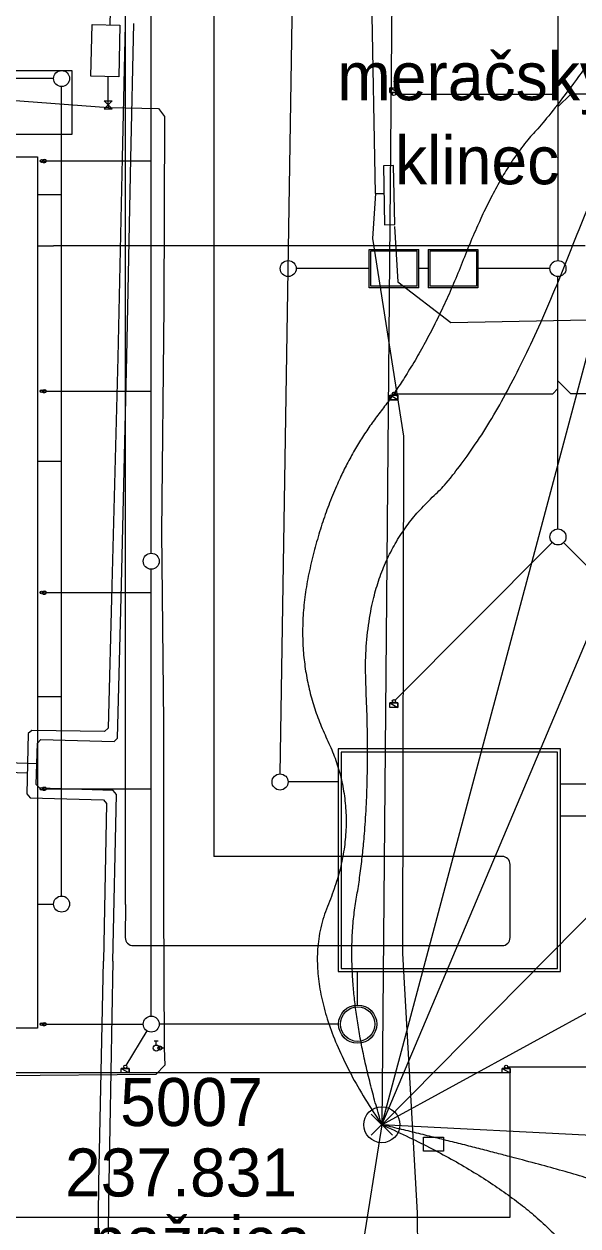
# Model space of a CAD drawing. Extents: x -264090 to -263500, y -1242327 to -1242030.
# Drawn here: x -263959.9 to -263925.3, y -1242264.5 to -1242189.5 of the extents above; entities that cross this region are included whole.
import ezdxf

# ---------------------------------------------------------------- set-up
doc = ezdxf.new("R2010")
doc.units = 0
for name, color, linetype in [('KFA_KOORD_SIT_a_IS_SEDA', 7, 'Continuous'), ('KFA_ZVS_BOD_CISLO', 7, 'Continuous'), ('KFA_ZVS_BOD_SYMBOL', 7, 'Continuous'), ('KFA_ZVS_BOD_VYSKA', 7, 'Continuous'), ('KFA_ZVS_NIVELACIA', 7, 'Continuous'), ('KFA_ZVS_POPIS', 7, 'Continuous'), ('KFA_ZVS_SMERY_A_DLZKY', 7, 'Continuous')]:
    doc.layers.add(name, color=color, linetype=linetype)

msp = doc.modelspace()

# ---------------------------------------------------------------- linework, layer by layer
at = {"layer": 'KFA_KOORD_SIT_a_IS_SEDA'}
for p, q in [((-263948.093, -1242087.901), (-263948.093, -1242241.458)), ((-263953.617, -1242244.458), (-263953.617, -1242093.307)), ((-263937.993, -1242200.068), (-263938.95, -1242148.666)), ((-263926.593, -1242155.252), (-263926.593, -1242204.252)), ((-263952, -1242222.527), (-263952, -1242182)), ((-263953.528, -1242183.799), (-263953.63, -1242189.514)), ((-263943.946, -1242236.311), (-263943.136, -1242185.245)), ((-263954.57, -1242189.535), (-263954.509, -1242186.913)), ((-263955.775, -1242192.739), (-263955.679, -1242189.503)), ((-263955.679, -1242189.503), (-263953.955, -1242189.552)), ((-263953.955, -1242189.552), (-263954.033, -1242192.766)), ((-263953.63, -1242189.514), (-263953.822, -1242197.849)), ((-263953.266, -1242197.902), (-263953.083, -1242189.456)), ((-263958.097, -1242192.883), (-263969.542, -1242192.883)), ((-263954.033, -1242192.766), (-263955.775, -1242192.739)), ((-263954.693, -1242194.518), (-263954.696, -1242192.756)), ((-263957.597, -1242243.932), (-263957.597, -1242193.383)), ((-263937.093, -1242193.752), (-263937.093, -1242193.462)), ((-263937.093, -1242193.462), (-263936.593, -1242193.462)), ((-263936.593, -1242193.752), (-263937.093, -1242193.462)), ((-263936.593, -1242193.752), (-263937.093, -1242193.462)), ((-263937.093, -1242193.462), (-263937.093, -1242193.752)), ((-263936.593, -1242193.752), (-263937.093, -1242193.752)), ((-263937.093, -1242193.752), (-263936.593, -1242193.752)), ((-263936.743, -1242193.852), (-263926.953, -1242193.852)), ((-263936.593, -1242193.462), (-263936.593, -1242193.752)), ((-263926.953, -1242193.852), (-263926.593, -1242194.178)), ((-263925.798, -1242193.852), (-263926.593, -1242194.648)), ((-263920.944, -1242193.852), (-263925.798, -1242193.852)), ((-263961.65, -1242194.164), (-263954.663, -1242194.7)), ((-263954.943, -1242194.268), (-263954.443, -1242194.268)), ((-263954.443, -1242194.268), (-263954.943, -1242194.768)), ((-263954.443, -1242194.768), (-263954.943, -1242194.268)), ((-263954.943, -1242194.768), (-263954.443, -1242194.768)), ((-263954.663, -1242194.7), (-263954.693, -1242194.518)), ((-263954.663, -1242194.7), (-263951.539, -1242194.754)), ((-263951.539, -1242194.754), (-263951.176, -1242195.243)), ((-263951.176, -1242195.243), (-263951.207, -1242207.105)), ((-263967.593, -1242197.782), (-263959.093, -1242197.782)), ((-263967.593, -1242197.782), (-263959.097, -1242197.782)), ((-263959.097, -1242197.782), (-263959.093, -1242252.182)), ((-263959.093, -1242197.782), (-263959.093, -1242252.182)), ((-263958.799, -1242197.962), (-263958.762, -1242197.962)), ((-263958.799, -1242198.102), (-263958.762, -1242198.102)), ((-263958.762, -1242197.962), (-263958.742, -1242197.942)), ((-263958.762, -1242198.102), (-263958.742, -1242198.122)), ((-263958.742, -1242197.942), (-263958.637, -1242197.942)), ((-263958.742, -1242198.122), (-263958.637, -1242198.122)), ((-263958.575, -1242198.032), (-263952, -1242198.032)), ((-263953.822, -1242197.849), (-263954.091, -1242210.31)), ((-263953.525, -1242210.24), (-263953.266, -1242197.902)), ((-263936.861, -1242198.305), (-263937.501, -1242198.334)), ((-263937.501, -1242198.334), (-263937.428, -1242202.028)), ((-263937.501, -1242198.334), (-263937.501, -1242198.334)), ((-263936.776, -1242202.003), (-263936.861, -1242198.305)), ((-263937.993, -1242200.068), (-263938.174, -1242202.878)), ((-263937.993, -1242200.068), (-263937.467, -1242200.068)), ((-263959.097, -1242200.132), (-263957.597, -1242200.132)), ((-263937.428, -1242202.028), (-263936.776, -1242202.003)), ((-263936.81, -1242202.117), (-263936.602, -1242205.569)), ((-263938.174, -1242202.878), (-263936.242, -1242215.207)), ((-263959.097, -1242203.332), (-263958.097, -1242203.332)), ((-263924.893, -1242203.332), (-263958.097, -1242203.332)), ((-263938.393, -1242203.552), (-263935.293, -1242203.552)), ((-263938.393, -1242205.952), (-263938.393, -1242203.552)), ((-263938.293, -1242205.852), (-263938.293, -1242203.652)), ((-263938.293, -1242203.652), (-263935.393, -1242203.652)), ((-263935.393, -1242205.852), (-263935.393, -1242203.652)), ((-263935.293, -1242205.952), (-263935.293, -1242203.552)), ((-263934.693, -1242203.552), (-263931.593, -1242203.552)), ((-263934.693, -1242203.552), (-263934.693, -1242205.952)), ((-263934.593, -1242203.652), (-263934.593, -1242205.852)), ((-263934.593, -1242203.652), (-263931.693, -1242203.652)), ((-263931.693, -1242203.652), (-263931.693, -1242205.852)), ((-263931.593, -1242203.552), (-263931.593, -1242205.952)), ((-263938.393, -1242204.752), (-263942.945, -1242204.752)), ((-263934.693, -1242204.752), (-263935.293, -1242204.752)), ((-263927.093, -1242204.752), (-263931.593, -1242204.752)), ((-263926.593, -1242221.011), (-263926.593, -1242205.252)), ((-263935.293, -1242205.952), (-263938.393, -1242205.952)), ((-263935.393, -1242205.852), (-263938.293, -1242205.852)), ((-263936.602, -1242205.569), (-263933.291, -1242208.127)), ((-263931.593, -1242205.952), (-263934.693, -1242205.952)), ((-263931.693, -1242205.852), (-263934.593, -1242205.852)), ((-263951.207, -1242207.105), (-263951.356, -1242221.201)), ((-263933.291, -1242208.127), (-263902.954, -1242207.498)), ((-263954.091, -1242210.31), (-263954.451, -1242224.536)), ((-263953.851, -1242224.476), (-263953.525, -1242210.24)), ((-263925.798, -1242212.562), (-263926.593, -1242211.767)), ((-263958.799, -1242212.337), (-263958.762, -1242212.337)), ((-263958.799, -1242212.477), (-263958.762, -1242212.477)), ((-263958.762, -1242212.337), (-263958.742, -1242212.317)), ((-263958.762, -1242212.477), (-263958.742, -1242212.497)), ((-263958.742, -1242212.317), (-263958.637, -1242212.317)), ((-263958.742, -1242212.497), (-263958.637, -1242212.497)), ((-263958.575, -1242212.407), (-263952, -1242212.407)), ((-263937.093, -1242212.952), (-263937.093, -1242212.662)), ((-263937.093, -1242212.662), (-263936.593, -1242212.662)), ((-263936.593, -1242212.952), (-263937.093, -1242212.662)), ((-263936.593, -1242212.952), (-263937.093, -1242212.662)), ((-263937.093, -1242212.662), (-263937.093, -1242212.952)), ((-263936.743, -1242212.562), (-263926.919, -1242212.562)), ((-263936.593, -1242212.662), (-263936.593, -1242212.952)), ((-263926.919, -1242212.562), (-263926.593, -1242212.237)), ((-263916.443, -1242212.562), (-263925.798, -1242212.562)), ((-263936.593, -1242212.952), (-263937.093, -1242212.952)), ((-263937.093, -1242212.952), (-263936.593, -1242212.952)), ((-263936.242, -1242215.207), (-263936.305, -1242247.518)), ((-263959.097, -1242216.782), (-263957.597, -1242216.782)), ((-263951.356, -1242221.201), (-263951.228, -1242233.09)), ((-263936.772, -1242231.691), (-263926.947, -1242221.865)), ((-263916.414, -1242231.691), (-263926.24, -1242221.865)), ((-263952, -1242251.432), (-263952, -1242223.527)), ((-263954.451, -1242224.536), (-263954.692, -1242233.447)), ((-263954.106, -1242234.073), (-263953.851, -1242224.476)), ((-263958.799, -1242224.912), (-263958.762, -1242224.912)), ((-263958.799, -1242225.052), (-263958.762, -1242225.052)), ((-263958.762, -1242224.912), (-263958.742, -1242224.892)), ((-263958.762, -1242225.052), (-263958.742, -1242225.072)), ((-263958.742, -1242224.892), (-263958.637, -1242224.892)), ((-263958.742, -1242225.072), (-263958.637, -1242225.072)), ((-263958.575, -1242224.982), (-263952, -1242224.982)), ((-263959.097, -1242231.482), (-263957.597, -1242231.482)), ((-263937.093, -1242231.862), (-263936.593, -1242231.862)), ((-263937.093, -1242232.152), (-263937.093, -1242231.862)), ((-263937.093, -1242231.862), (-263936.593, -1242232.152)), ((-263937.093, -1242231.862), (-263936.593, -1242232.152)), ((-263936.593, -1242231.862), (-263937.093, -1242231.862)), ((-263936.593, -1242232.152), (-263937.093, -1242232.152)), ((-263936.593, -1242231.862), (-263936.593, -1242232.152)), ((-263936.593, -1242232.152), (-263936.593, -1242231.862)), ((-263951.228, -1242233.09), (-263951.241, -1242244.319)), ((-263959.696, -1242233.784), (-263959.771, -1242237.559)), ((-263959.451, -1242233.59), (-263959.696, -1242233.784)), ((-263954.912, -1242233.658), (-263959.451, -1242233.59)), ((-263954.692, -1242233.447), (-263954.912, -1242233.658)), ((-263959.189, -1242236.963), (-263959.11, -1242234.394)), ((-263959.11, -1242234.394), (-263958.895, -1242234.164)), ((-263958.895, -1242234.164), (-263954.308, -1242234.275)), ((-263954.308, -1242234.275), (-263954.106, -1242234.073)), ((-263926.43, -1242234.749), (-263940.33, -1242234.749)), ((-263940.33, -1242234.749), (-263940.33, -1242248.649)), ((-263926.63, -1242234.949), (-263940.13, -1242234.949)), ((-263940.13, -1242234.949), (-263940.13, -1242248.449)), ((-263926.63, -1242248.449), (-263926.63, -1242234.949)), ((-263926.43, -1242248.649), (-263926.43, -1242234.749)), ((-263959.149, -1242235.676), (-263963.972, -1242235.519)), ((-263959.745, -1242236.267), (-263963.952, -1242236.1)), ((-263940.33, -1242236.811), (-263943.454, -1242236.811)), ((-263959.771, -1242237.559), (-263959.557, -1242237.791)), ((-263958.966, -1242237.191), (-263959.189, -1242236.963)), ((-263954.387, -1242237.352), (-263958.966, -1242237.191)), ((-263958.799, -1242237.162), (-263958.762, -1242237.162)), ((-263958.799, -1242237.302), (-263958.762, -1242237.302)), ((-263958.762, -1242237.162), (-263958.742, -1242237.142)), ((-263958.762, -1242237.302), (-263958.742, -1242237.322)), ((-263958.742, -1242237.142), (-263958.637, -1242237.142)), ((-263958.742, -1242237.322), (-263958.637, -1242237.322)), ((-263958.575, -1242237.232), (-263952, -1242237.232)), ((-263954.408, -1242247.997), (-263954.173, -1242237.595)), ((-263954.173, -1242237.595), (-263954.387, -1242237.352)), ((-263919.13, -1242236.949), (-263926.43, -1242236.949)), ((-263959.557, -1242237.791), (-263954.983, -1242237.917)), ((-263954.983, -1242237.917), (-263954.788, -1242238.153)), ((-263954.788, -1242238.153), (-263954.978, -1242247.991)), ((-263907.219, -1242238.949), (-263926.43, -1242238.949)), ((-263930.081, -1242241.458), (-263948.093, -1242241.458)), ((-263929.582, -1242246.53), (-263929.581, -1242241.959)), ((-263951.241, -1242244.319), (-263951.192, -1242253.436)), ((-263959.097, -1242244.432), (-263958.097, -1242244.432)), ((-263953.617, -1242244.458), (-263953.619, -1242246.529)), ((-263953.119, -1242247.03), (-263930.082, -1242247.03)), ((-263955.264, -1242261.849), (-263954.978, -1242247.991)), ((-263954.408, -1242247.997), (-263954.644, -1242261.82)), ((-263936.305, -1242247.518), (-263935.392, -1242263.705)), ((-263940.33, -1242248.649), (-263926.43, -1242248.649)), ((-263940.13, -1242248.449), (-263926.63, -1242248.449)), ((-263939.13, -1242248.649), (-263939.13, -1242250.737)), ((-263958.799, -1242251.862), (-263958.762, -1242251.862)), ((-263958.762, -1242251.862), (-263958.742, -1242251.842)), ((-263958.742, -1242251.842), (-263958.637, -1242251.842)), ((-263959.093, -1242252.182), (-263967.593, -1242252.182)), ((-263959.093, -1242252.182), (-263967.593, -1242252.182)), ((-263958.799, -1242252.002), (-263958.762, -1242252.002)), ((-263958.762, -1242252.002), (-263958.742, -1242252.022)), ((-263958.742, -1242252.022), (-263958.637, -1242252.022)), ((-263958.575, -1242251.932), (-263952.5, -1242251.932)), ((-263953.57, -1242254.506), (-263952.26, -1242252.359)), ((-263940.302, -1242251.932), (-263951.5, -1242251.932)), ((-263951.562, -1242252.985), (-263951.812, -1242252.985)), ((-263951.687, -1242253.235), (-263951.687, -1242252.985)), ((-263951.192, -1242253.436), (-263951.461, -1242253.427)), ((-263951.192, -1242253.436), (-263951.15, -1242254.486)), ((-263953.87, -1242254.692), (-263953.37, -1242254.692)), ((-263953.87, -1242254.982), (-263953.87, -1242254.692)), ((-263953.87, -1242254.692), (-263953.37, -1242254.982)), ((-263953.87, -1242254.692), (-263953.37, -1242254.982)), ((-263953.37, -1242254.692), (-263953.87, -1242254.692)), ((-263953.37, -1242254.692), (-263953.37, -1242254.982)), ((-263953.37, -1242254.982), (-263953.37, -1242254.692)), ((-263951.15, -1242254.486), (-263951.718, -1242255.083)), ((-263930.08, -1242254.692), (-263929.58, -1242254.692)), ((-263930.08, -1242254.982), (-263930.08, -1242254.692)), ((-263930.08, -1242254.692), (-263929.58, -1242254.982)), ((-263930.08, -1242254.692), (-263929.58, -1242254.982)), ((-263929.58, -1242254.692), (-263930.08, -1242254.692)), ((-263929.73, -1242254.592), (-263920.595, -1242254.592)), ((-263929.58, -1242254.692), (-263929.58, -1242254.982)), ((-263929.58, -1242254.982), (-263929.58, -1242254.692)), ((-263951.718, -1242255.083), (-263961.355, -1242255.168)), ((-263953.37, -1242254.982), (-263953.87, -1242254.982)), ((-263929.58, -1242254.982), (-263930.08, -1242254.982)), ((-263934.994, -1242258.986), (-263933.751, -1242258.986)), ((-263934.994, -1242259.867), (-263934.994, -1242258.986)), ((-263933.751, -1242258.986), (-263933.751, -1242259.867)), ((-263933.751, -1242259.867), (-263934.994, -1242259.867)), ((-263955.442, -1242275.089), (-263955.264, -1242261.849)), ((-263954.644, -1242261.82), (-263954.858, -1242275.059)), ((-263935.392, -1242263.705), (-263934.919, -1242303.408))]:
    msp.add_line(p, q, dxfattribs=at)
for points in [[(-263961.968, -1242192.382), (-263956.968, -1242192.382), (-263956.968, -1242196.382), (-263961.968, -1242196.382)], [(-263967.597, -1242197.782), (-263959.097, -1242197.782), (-263959.097, -1242252.182), (-263967.597, -1242252.182)]]:
    msp.add_lwpolyline(points, close=True, dxfattribs=at)
msp.add_lwpolyline([(-263929.58, -1242254.982), (-263970.077, -1242254.982), (-263970.077, -1242263.982), (-263929.58, -1242263.982), (-263929.58, -1242254.982)], dxfattribs=at)
for centre, radius in [((-263957.597, -1242192.883), 0.5), ((-263936.843, -1242193.852), 0.1), ((-263958.847, -1242198.032), 0.085), ((-263958.847, -1242198.032), 0.0625), ((-263958.637, -1242198.032), 0.0625), ((-263943.445, -1242204.752), 0.5), ((-263926.593, -1242204.752), 0.5), ((-263958.847, -1242212.407), 0.085), ((-263958.847, -1242212.407), 0.0625), ((-263958.637, -1242212.407), 0.0625), ((-263936.843, -1242212.562), 0.1), ((-263926.593, -1242221.511), 0.5), ((-263952, -1242223.027), 0.5), ((-263958.847, -1242224.982), 0.085), ((-263958.847, -1242224.982), 0.0625), ((-263958.637, -1242224.982), 0.0625), ((-263936.843, -1242231.762), 0.1), ((-263943.954, -1242236.811), 0.5), ((-263958.847, -1242237.232), 0.085), ((-263958.847, -1242237.232), 0.0625), ((-263958.637, -1242237.232), 0.0625), ((-263957.597, -1242244.432), 0.5), ((-263939.107, -1242251.932), 1.195), ((-263939.107, -1242251.932), 1.075), ((-263958.847, -1242251.932), 0.085), ((-263958.847, -1242251.932), 0.0625), ((-263958.637, -1242251.932), 0.0625), ((-263952, -1242251.932), 0.5), ((-263951.687, -1242253.423), 0.188), ((-263951.461, -1242253.427), 0.125), ((-263953.62, -1242254.592), 0.1), ((-263929.83, -1242254.592), 0.1)]:
    msp.add_circle(centre, radius, dxfattribs=at)
for centre, radius, start, end in [((-263958.637, -1242198.032), 0.09, 270, 90), ((-263958.637, -1242212.407), 0.09, 270, 90), ((-263958.637, -1242224.982), 0.09, 270, 90), ((-263958.637, -1242237.232), 0.09, 270, 90), ((-263930.081, -1242241.958), 0.5, 359.97854, 89.99994), ((-263953.119, -1242246.53), 0.5, 179.95255, 270), ((-263930.082, -1242246.53), 0.5, 270, 359.97854), ((-263958.637, -1242251.932), 0.09, 270, 90)]:
    msp.add_arc(centre, radius, start, end, dxfattribs=at)
at = {"layer": 'KFA_ZVS_BOD_SYMBOL'}
for p, q in [((-263938.263, -1242258.874), (-263936.937, -1242257.548)), ((-263936.937, -1242258.874), (-263938.263, -1242257.548))]:
    msp.add_line(p, q, dxfattribs=at)
msp.add_circle((-263937.6, -1242258.211), 1.125, dxfattribs=at)
at = {"layer": 'KFA_ZVS_NIVELACIA'}
for points in [[(-263916.904, -1242180.641), (-263925.798, -1242193.852), (-263930.312, -1242198.613), (-263934.768, -1242209.95), (-263940.766, -1242217.665), (-263943.387, -1242229.195), (-263938.661, -1242239.053), (-263943.261, -1242249.943), (-263937.6, -1242258.211)], [(-263937.6, -1242258.211), (-263940.179, -1242249.78), (-263938.22, -1242238.563), (-263938.948, -1242223.279), (-263930.232, -1242215.099), (-263920.849, -1242190.894), (-263913.063, -1242187.955), (-263916.904, -1242180.641)], [(-263937.6, -1242258.211), (-263928.936, -1242262.063), (-263922.038, -1242271.064), (-263908.691, -1242276.165), (-263901.493, -1242267.314), (-263884.997, -1242267.314), (-263876.149, -1242269.264), (-263867.589, -1242264.788), (-263858.267, -1242262.294)], [(-263858.267, -1242262.294), (-263872.503, -1242264.923), (-263878.722, -1242267.127), (-263884.99, -1242265.854), (-263892.335, -1242262.572), (-263906.067, -1242264.914), (-263907.585, -1242268.147), (-263919.043, -1242268.147), (-263920.708, -1242262.66), (-263931.12, -1242259.749), (-263937.6, -1242258.211)]]:
    msp.add_open_spline(points, degree=2, dxfattribs=at)
at = {"layer": 'KFA_ZVS_SMERY_A_DLZKY'}
for p, q in [((-263937.6, -1242258.211), (-263845.523, -1242040.303)), ((-263779.167, -1242098.021), (-263937.6, -1242258.211)), ((-263937.6, -1242258.211), (-263768.002, -1242165.53)), ((-263936.802, -1242167.947), (-263937.6, -1242258.211)), ((-263937.6, -1242258.211), (-263916.904, -1242180.641)), ((-263937.6, -1242258.211), (-263946.283, -1242313.43)), ((-263858.267, -1242262.294), (-263937.6, -1242258.211))]:
    msp.add_line(p, q, dxfattribs=at)

# ---------------------------------------------------------------- texts
at = {"layer": 'KFA_ZVS_BOD_CISLO'}
msp.add_text('5007', height=3, dxfattribs=at).set_placement((-263953.941, -1242258.297))
at = {"layer": 'KFA_ZVS_BOD_VYSKA'}
msp.add_text('237.831', height=3, dxfattribs=at).set_placement((-263957.387, -1242262.695))
at = {"layer": 'KFA_ZVS_POPIS'}
for s, p in [('meračský', (-263940.38, -1242194.236)), ('klinec', (-263936.771, -1242199.486)), ('pažnica', (-263955.82, -1242266.958))]:
    msp.add_text(s, height=3, dxfattribs=at).set_placement(p)

doc.saveas('drawing.dxf')
